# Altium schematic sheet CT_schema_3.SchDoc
size 461 x 327 mm
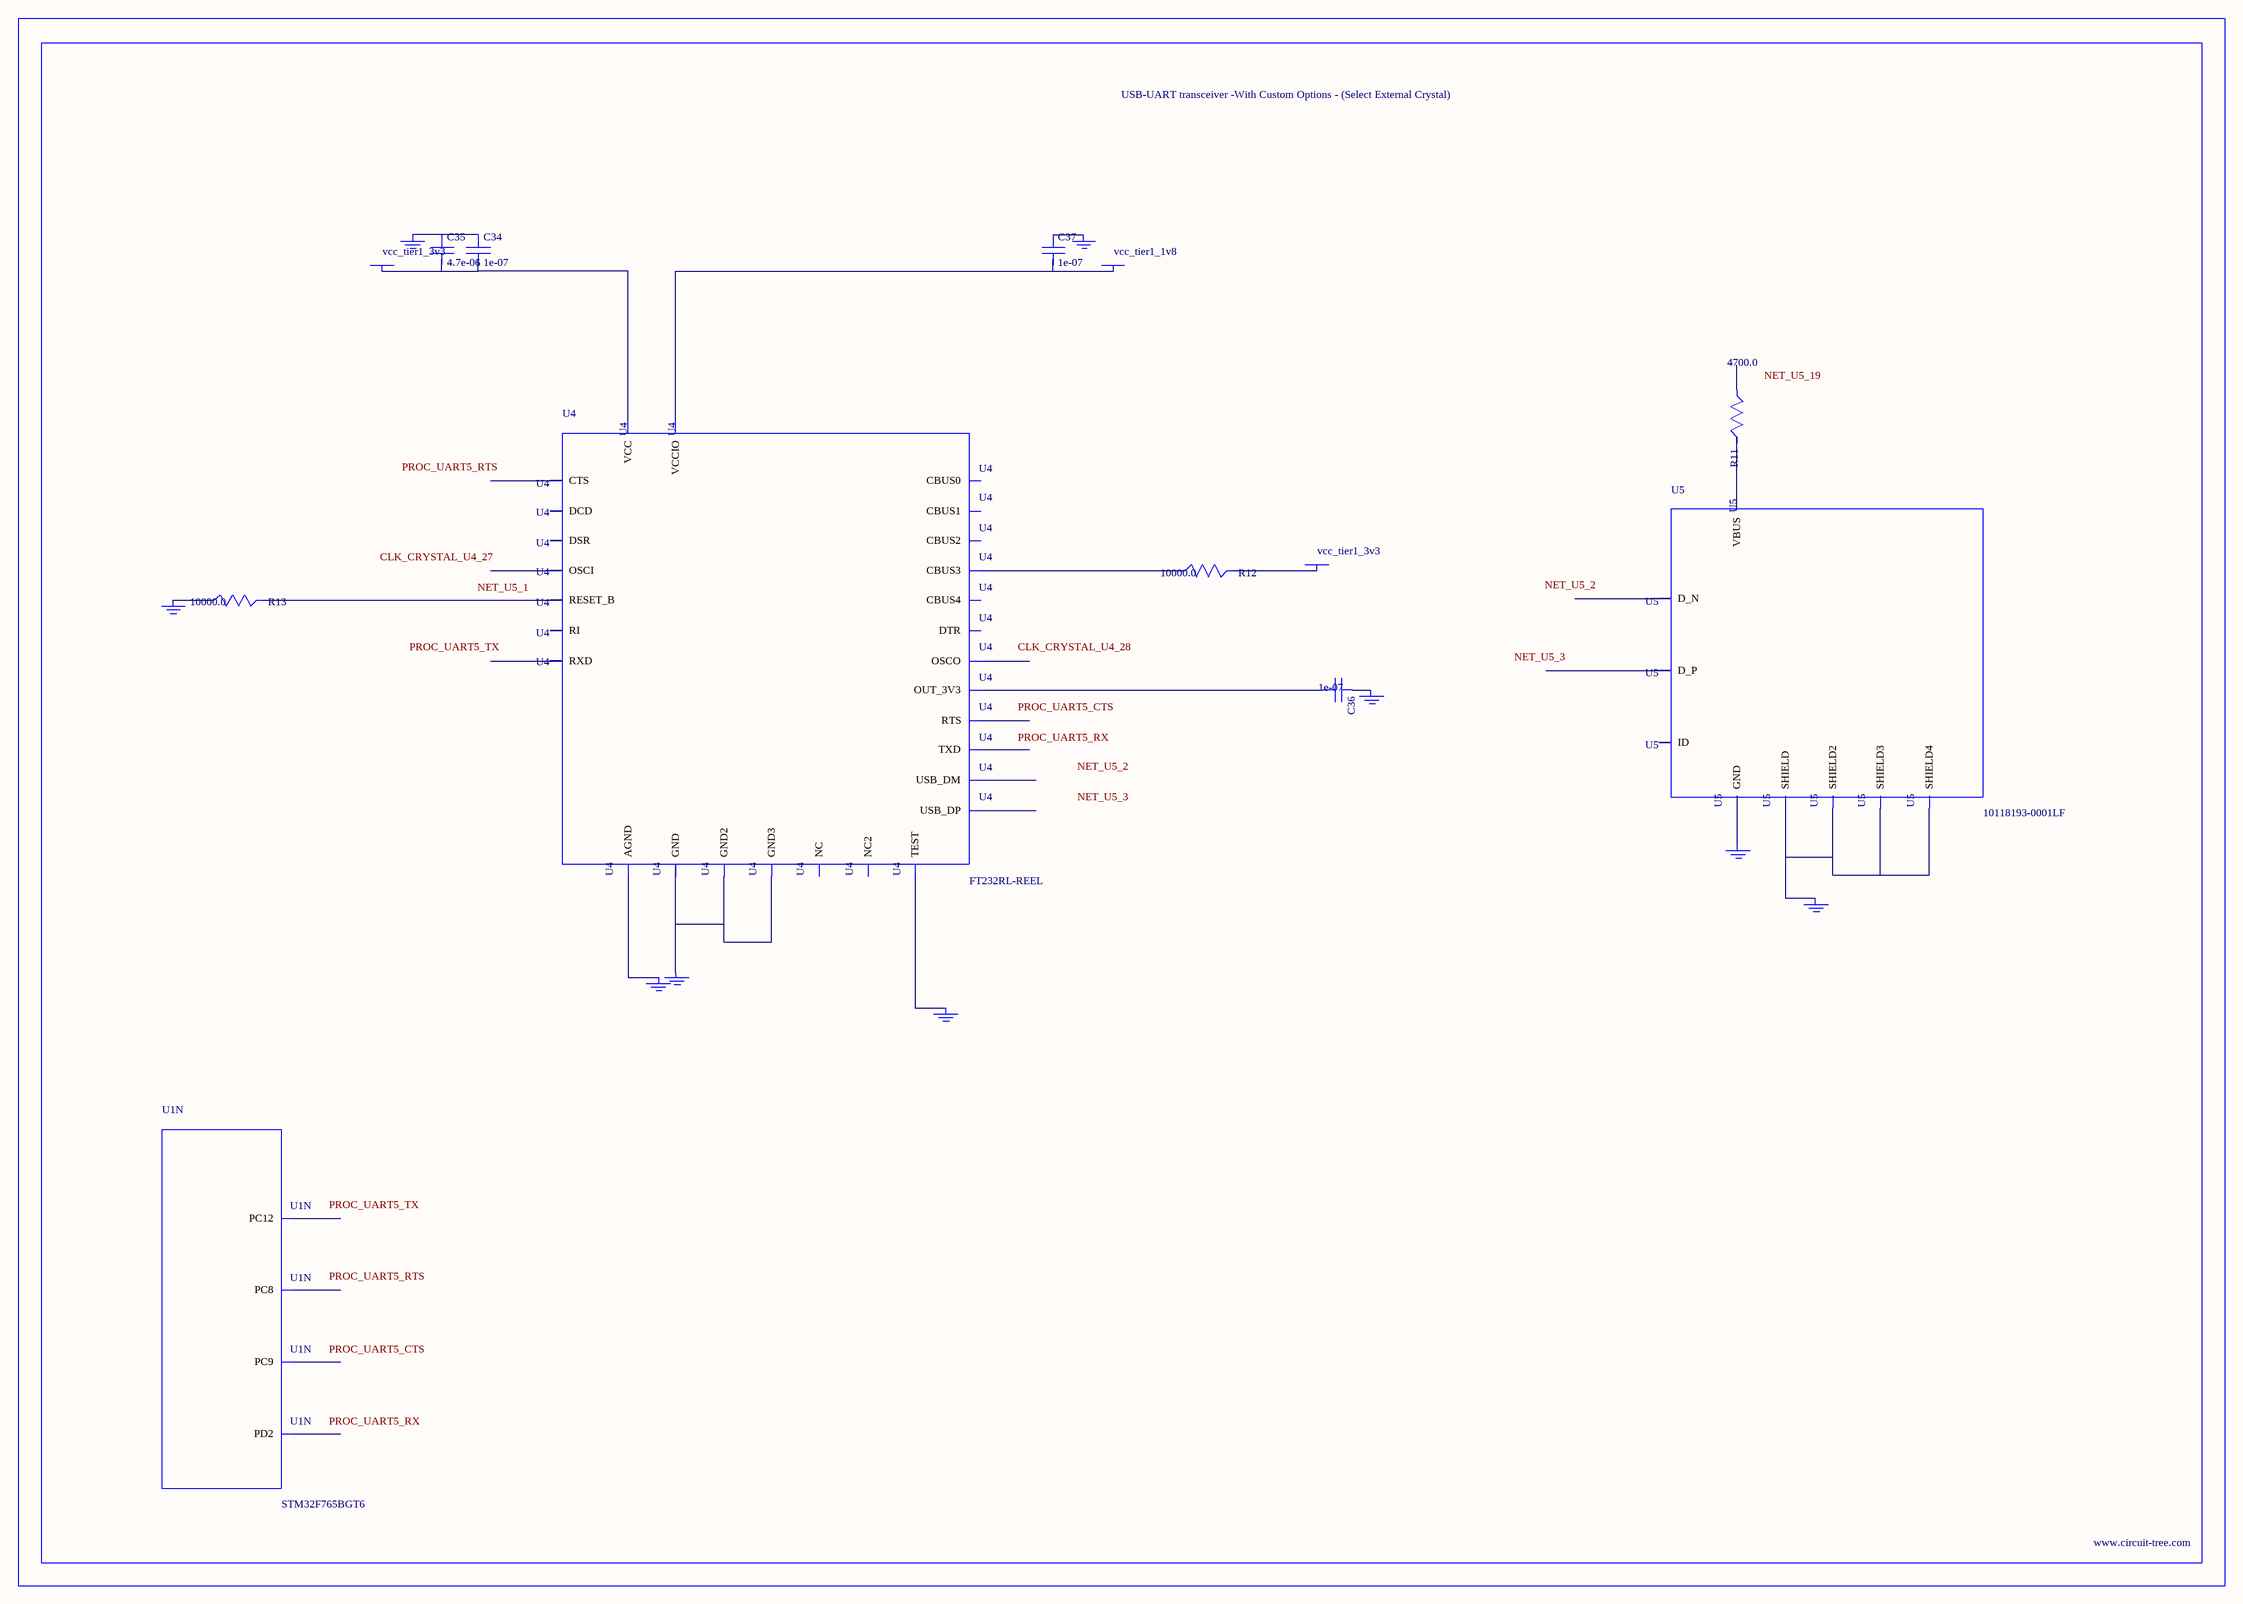
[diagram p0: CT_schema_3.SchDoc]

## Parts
BORDER2  (no value)
C34  1e-07  [C0402]
C35  4.7e-06  [C0805]
C36  1e-07  [C0402]
C37  1e-07  [C0402]
GND_INSTANCE_2_0  (no value)
GND_INSTANCE_2_1  (no value)
GND_INSTANCE_2_2  (no value)
GND_INSTANCE_2_3  (no value)
GND_INSTANCE_2_4  (no value)
GND_INSTANCE_2_5  (no value)
GND_INSTANCE_2_6  (no value)
GND_INSTANCE_2_7  (no value)
GND_INSTANCE_2_8  (no value)
POWER_INSTANCE_2_0  vcc_tier1_1v8
POWER_INSTANCE_2_1  vcc_tier1_3v3
POWER_INSTANCE_2_2  vcc_tier1_3v3
R11  4700.0  [R0603]
R12  10000.0  [R0603]
R13  10000.0  [R0603]
U1  STM32F765BGT6  [LQFP208]  (part N of 16)
U4  FT232RL-REEL  [SSOP-28]
U5  10118193-0001LF  [FCI_10118193-0001LF]

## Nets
NetC34_1: C34.1 C35.1 GND_INSTANCE_2_3.0(GND)
NetC34_2: C34.2 C35.2 POWER_INSTANCE_2_2.0(PWR) U4.20(VCC)
NetC36_1: C36.1 GND_INSTANCE_2_1.0(GND)
NetC36_2: C36.2 U4.17(OUT_3V3)
NetC37_1: C37.1 GND_INSTANCE_2_0.0(GND)
NetC37_2: C37.2 POWER_INSTANCE_2_0.0(PWR) U4.4(VCCIO)
NetGND_INSTANCE_2_2_0: GND_INSTANCE_2_2.0(GND) R13.1
NetGND_INSTANCE_2_4_0: GND_INSTANCE_2_4.0(GND) U4.25(AGND)
NetGND_INSTANCE_2_5_0: GND_INSTANCE_2_5.0(GND) U4.26(TEST)
NetGND_INSTANCE_2_6_0: GND_INSTANCE_2_6.0(GND) U4.7(GND) U4.18(GND2) U4.21(GND3)
NetGND_INSTANCE_2_7_0: GND_INSTANCE_2_7.0(GND) U5.6(SHIELD) U5.7(SHIELD2) U5.8(SHIELD3) U5.9(SHIELD4)
NetGND_INSTANCE_2_8_0: GND_INSTANCE_2_8.0(GND) U5.5(GND)
NetPOWER_INSTANCE_2_1_0: POWER_INSTANCE_2_1.0(PWR) R12.2
NetR11_2: R11.2 U5.1(VBUS)
NetR12_1: R12.1 U4.14(CBUS3)
NetR13_2: R13.2 U4.19(RESET_B)

Not connected (* = marked no-connect by the designer): R11 1; U1 140(PC8) 141(PC9) 163(PC12) 166(PD2); U4 1(TXD) 2(DTR) 3(RTS) 5(RXD) 6(RI) 8(NC) 9(DSR) 10(DCD) 11(CTS) 12(CBUS4) 13(CBUS2) 15(USB_DP) 16(USB_DM) 22(CBUS1) 23(CBUS0) 24(NC2) 27(OSCI) 28(OSCO); U5 2(D_N) 3(D_P) 4(ID)

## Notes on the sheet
- Labels drawn without touching a wire or pin: CLK_CRYSTAL_U4_27, CLK_CRYSTAL_U4_28, NET_U5_1, NET_U5_2, NET_U5_3, NET_U5_19, PROC_UART5_CTS, PROC_UART5_RTS, PROC_UART5_RX, PROC_UART5_TX

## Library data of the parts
BORDER2 = BORDER_PAGE2
C34 C36 C37 = C0402C104K3RACTU
C35 = C0805C475K4RACTU
GND_INSTANCE_2_0-GND_INSTANCE_2_8 = GND
POWER_INSTANCE_2_0-POWER_INSTANCE_2_2 = PWR
R11 = RC0603JR-074K7L
R12 R13 = RC0603JR-0710KL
